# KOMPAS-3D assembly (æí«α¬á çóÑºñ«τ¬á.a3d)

Referenced files in D:\МОДЕЛЬ ТАНКА Т90\ДЕТАЛИ\ХОДОВАЯ\звездочка\: ведущая звездочка.m3d, диск звездочки.m3d, ведущая звездочка1.m3d
Referenced files in D:\МОДЕЛЬ ТАНКА Т90\ДЕТАЛИ\ХОДОВАЯ\Каток опорный с балансиром\: шпилька соеденения катков.m3d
